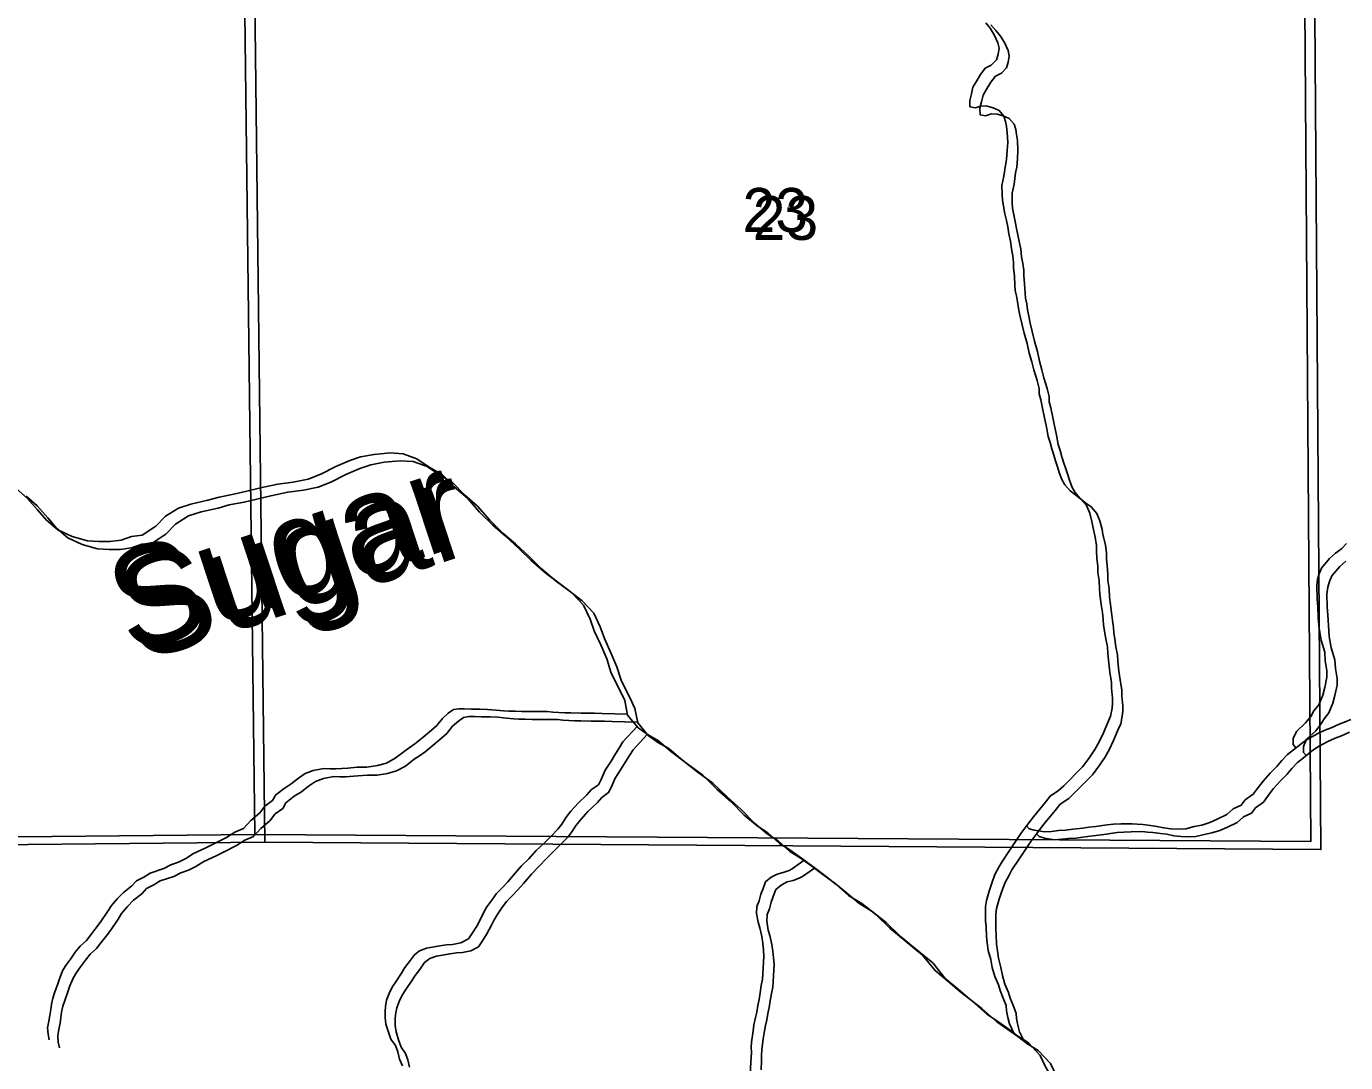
# Model space of a CAD drawing. Extents: x -21.1 to 50.3, y 0 to 22.1.
# Drawn here: x 47.981 to 49.235, y 15.452 to 16.437 of the extents above; entities that cross this region are included whole.
import ezdxf

# ---------------------------------------------------------------- set-up
doc = ezdxf.new("R2010")
doc.units = 0
for name, color, linetype in [('GM_X_Major_River', 7, 'Continuous'), ('GM_X_Major_River_Text', 7, 'Continuous'), ('GM_X_Minor_River', 7, 'Continuous'), ('GM_X_Section', 7, 'Continuous'), ('GM_X_Section_Text', 7, 'Continuous')]:
    doc.layers.add(name, color=color, linetype=linetype)

msp = doc.modelspace()

# ---------------------------------------------------------------- linework, layer by layer
at = {"layer": 'GM_X_Major_River'}
for points in [[(47.9706, 15.998), (47.9813, 15.9886), (47.9913, 15.9773), (47.9997, 15.9675), (48.0104, 15.9584), (48.0241, 15.9521), (48.0386, 15.948), (48.0496, 15.9474), (48.0602, 15.9474), (48.0708, 15.9487), (48.0806, 15.9522), (48.0905, 15.9534), (48.1037, 15.9618), (48.1127, 15.9714), (48.1252, 15.9791), (48.1369, 15.983), (48.1532, 15.9865), (48.1638, 15.9896), (48.1778, 15.9924), (48.19, 15.9951), (48.2032, 15.9983), (48.2195, 16.0018), (48.2343, 16.0038), (48.2483, 16.0066), (48.2604, 16.0112), (48.2748, 16.0186), (48.288, 16.0244), (48.2982, 16.0278), (48.3111, 16.0302), (48.3263, 16.0315), (48.3388, 16.0308), (48.3517, 16.026), (48.3636, 16.0181), (48.3761, 16.0106), (48.3872, 15.9993), (48.3999, 15.9884), (48.4113, 15.9752), (48.424, 15.9628), (48.4358, 15.9527), (48.4492, 15.9402), (48.4603, 15.9293), (48.4748, 15.9169), (48.487, 15.9079), (48.4992, 15.8985), (48.5103, 15.8868), (48.5165, 15.8736), (48.5204, 15.8626), (48.5266, 15.849), (48.5324, 15.8358), (48.5366, 15.8221), (48.5447, 15.8059), (48.5494, 15.7961), (48.5521, 15.7824), (48.5621, 15.7704), (48.5716, 15.7636), (48.5815, 15.758), (48.593, 15.7482), (48.6083, 15.7362), (48.6235, 15.7253), (48.6373, 15.7118), (48.6503, 15.7001), (48.6629, 15.6873), (48.6751, 15.6771), (48.6854, 15.6704), (48.6965, 15.6602), (48.7064, 15.6542), (48.7175, 15.6464), (48.7282, 15.6385), (48.7396, 15.6298), (48.7503, 15.6212), (48.7622, 15.611), (48.7748, 15.6032), (48.7881, 15.5927), (48.8015, 15.5799), (48.816, 15.5678), (48.8325, 15.5543), (48.8443, 15.5396), (48.8566, 15.5294), (48.8676, 15.52), (48.8791, 15.511), (48.8936, 15.4982), (48.9039, 15.4911), (48.9135, 15.4844), (48.923, 15.4772)], [(47.9803, 15.9905), (47.9909, 15.9811), (48.0009, 15.9698), (48.0093, 15.96), (48.02, 15.9509), (48.0337, 15.9446), (48.0482, 15.9405), (48.0592, 15.9399), (48.0698, 15.9399), (48.0804, 15.9412), (48.0903, 15.9447), (48.1001, 15.9459), (48.1133, 15.9543), (48.1224, 15.9639), (48.1348, 15.9716), (48.1466, 15.9754), (48.1629, 15.979), (48.1735, 15.9821), (48.1875, 15.9849), (48.1996, 15.9876), (48.2129, 15.9908), (48.2291, 15.9943), (48.2439, 15.9963), (48.2579, 15.9991), (48.27, 16.0037), (48.2844, 16.0111), (48.2976, 16.0169), (48.3079, 16.0203), (48.3207, 16.0227), (48.3359, 16.024), (48.3484, 16.0233), (48.3614, 16.0185), (48.3732, 16.0106), (48.3858, 16.0031), (48.3969, 15.9918), (48.4095, 15.9809), (48.421, 15.9677), (48.4336, 15.9553), (48.4454, 15.9452), (48.4588, 15.9327), (48.4699, 15.9218), (48.4844, 15.9094), (48.4966, 15.9004), (48.5089, 15.891), (48.52, 15.8793), (48.5261, 15.8661), (48.53, 15.8551), (48.5362, 15.8415), (48.542, 15.8283), (48.5463, 15.8146), (48.5544, 15.7984), (48.559, 15.7886), (48.5618, 15.7749), (48.5717, 15.7629), (48.5813, 15.7561), (48.5912, 15.7505), (48.6026, 15.7407), (48.6179, 15.7287), (48.6332, 15.7178), (48.6469, 15.7043), (48.6599, 15.6926), (48.6726, 15.6798), (48.6848, 15.6696), (48.6951, 15.6629), (48.7062, 15.6527), (48.7161, 15.6467), (48.7271, 15.6389), (48.7378, 15.631), (48.7493, 15.6223), (48.76, 15.6137), (48.7718, 15.6035), (48.7844, 15.5957), (48.7978, 15.5852), (48.8112, 15.5724), (48.8257, 15.5603), (48.8421, 15.5468), (48.854, 15.5321), (48.8662, 15.5219), (48.8773, 15.5125), (48.8887, 15.5035), (48.9032, 15.4907), (48.9136, 15.4836), (48.9231, 15.4769), (48.9326, 15.4697)], [(48.923, 15.4772), (48.9329, 15.4712), (48.9444, 15.4588), (48.9494, 15.4482), (48.9552, 15.438), (48.961, 15.4248), (48.9675, 15.4104), (48.9722, 15.3987), (48.978, 15.3824), (48.9807, 15.3726), (48.9869, 15.3609), (48.9984, 15.3477), (49.0079, 15.3405), (49.0201, 15.3342), (49.0369, 15.3244), (49.0464, 15.3207), (49.0579, 15.3136), (49.0701, 15.3069), (49.0838, 15.3002), (49.1033, 15.2925)], [(48.9326, 15.4697), (48.9425, 15.4637), (48.954, 15.4513), (48.959, 15.4407), (48.9648, 15.4305), (48.9706, 15.4173), (48.9772, 15.4029), (48.9818, 15.3912), (48.9876, 15.3749), (48.9904, 15.3651), (48.9965, 15.3534), (49.008, 15.3402), (49.0176, 15.333), (49.0298, 15.3267), (49.0465, 15.3169), (49.0561, 15.3132), (49.0675, 15.3061), (49.0797, 15.2994), (49.0934, 15.2927), (49.1129, 15.285)]]:
    msp.add_lwpolyline(points, dxfattribs=at)
at = {"layer": 'GM_X_Minor_River'}
for points in [[(48.9182, 16.219), (48.917, 16.2255), (48.9162, 16.2327), (48.9146, 16.2399), (48.9135, 16.2464), (48.9123, 16.2524), (48.9107, 16.2589), (48.9084, 16.2718), (48.908, 16.2771), (48.9079, 16.2858), (48.9098, 16.2946), (48.9112, 16.3052), (48.9123, 16.3105), (48.913, 16.3189), (48.9134, 16.3265), (48.913, 16.336), (48.9122, 16.3417), (48.9114, 16.3466), (48.9098, 16.3516), (48.9052, 16.3569), (48.8995, 16.3595), (48.8938, 16.361), (48.8885, 16.3613), (48.8828, 16.3594), (48.8774, 16.3605), (48.8774, 16.3666), (48.8789, 16.3727), (48.8804, 16.3791), (48.8834, 16.3841), (48.8875, 16.3913), (48.8921, 16.3971), (48.8977, 16.4001), (48.9027, 16.4051), (48.9042, 16.4104), (48.9053, 16.4161), (48.9041, 16.4214), (48.9006, 16.429), (48.8968, 16.4351), (48.8926, 16.4404)], [(48.9278, 16.2115), (48.9266, 16.218), (48.9258, 16.2252), (48.9243, 16.2324), (48.9231, 16.2389), (48.9219, 16.2449), (48.9204, 16.2514), (48.918, 16.2643), (48.9176, 16.2696), (48.9175, 16.2783), (48.9194, 16.2871), (48.9209, 16.2977), (48.922, 16.303), (48.9227, 16.3114), (48.923, 16.319), (48.9226, 16.3285), (48.9218, 16.3342), (48.921, 16.3391), (48.9195, 16.3441), (48.9149, 16.3494), (48.9091, 16.352), (48.9034, 16.3535), (48.8981, 16.3538), (48.8924, 16.3519), (48.8871, 16.353), (48.887, 16.3591), (48.8885, 16.3652), (48.89, 16.3716), (48.893, 16.3766), (48.8972, 16.3838), (48.9017, 16.3896), (48.9074, 16.3926), (48.9123, 16.3976), (48.9138, 16.4029), (48.9149, 16.4086), (48.9137, 16.4139), (48.9103, 16.4215), (48.9064, 16.4276), (48.9022, 16.4329), (48.8972, 16.4385)], [(48.9193, 15.48), (48.915, 15.4889), (48.9135, 15.495), (48.9123, 15.5014), (48.9119, 15.5063), (48.9092, 15.5132), (48.9061, 15.5207), (48.9045, 15.5261), (48.9011, 15.534), (48.8987, 15.5424), (48.8972, 15.55), (48.8948, 15.5587), (48.894, 15.5659), (48.8932, 15.572), (48.8928, 15.5811), (48.8924, 15.5868), (48.8923, 15.6004), (48.8931, 15.6061), (48.8957, 15.6149), (48.8983, 15.6225), (48.9013, 15.6309), (48.9051, 15.6377), (48.9077, 15.6427), (48.9145, 15.6526), (48.9258, 15.6698), (48.9315, 15.6774), (48.9379, 15.6858), (48.9492, 15.6995), (48.9538, 15.7053), (48.9617, 15.7106), (48.9667, 15.7152), (48.9845, 15.7332), (48.9905, 15.7412), (48.9962, 15.7496), (49.0003, 15.7568), (49.0045, 15.7656), (49.0086, 15.7754), (49.0112, 15.7815), (49.0127, 15.7888), (49.013, 15.7937), (49.013, 15.7986), (49.0122, 15.8081), (49.0122, 15.8135), (49.0106, 15.8233), (49.0094, 15.8317), (49.0086, 15.8408), (49.0082, 15.8472), (49.0066, 15.8548), (49.0054, 15.862), (49.0046, 15.8681), (49.0042, 15.8731), (49.0034, 15.8799), (49.0022, 15.8875), (49.001, 15.8973), (49.0006, 15.9023), (49.0002, 15.9103), (48.999, 15.9179), (48.999, 15.9235), (48.9982, 15.9319), (48.9978, 15.938), (48.9977, 15.9437), (48.9966, 15.9516), (48.9942, 15.9615), (48.9934, 15.9664), (48.9915, 15.9744), (48.9884, 15.9816), (48.983, 15.9877), (48.9781, 15.9914), (48.9727, 15.9956), (48.9677, 16.0013), (48.965, 16.0062), (48.9623, 16.013), (48.9608, 16.0183), (48.9589, 16.024), (48.9573, 16.0293), (48.9554, 16.0354), (48.9538, 16.0414), (48.9519, 16.0471), (48.9503, 16.0559), (48.948, 16.0665), (48.9468, 16.0726), (48.9448, 16.082), (48.9433, 16.0877), (48.9432, 16.0927), (48.9413, 16.1003), (48.9382, 16.1105), (48.9362, 16.1181), (48.9339, 16.1264), (48.932, 16.1355), (48.9292, 16.1454), (48.9269, 16.1545), (48.925, 16.1625), (48.9238, 16.1689), (48.9226, 16.175), (48.9218, 16.1807), (48.9206, 16.186), (48.9202, 16.1909), (48.9198, 16.1997), (48.919, 16.2076), (48.919, 16.2126), (48.9182, 16.219)], [(48.929, 15.4725), (48.9247, 15.4814), (48.9231, 15.4875), (48.9219, 15.4939), (48.9215, 15.4988), (48.9188, 15.5057), (48.9157, 15.5132), (48.9142, 15.5186), (48.9107, 15.5265), (48.9084, 15.5349), (48.9068, 15.5425), (48.9045, 15.5512), (48.9037, 15.5584), (48.9029, 15.5645), (48.9025, 15.5736), (48.902, 15.5793), (48.902, 15.5929), (48.9027, 15.5986), (48.9053, 15.6074), (48.9079, 15.615), (48.9109, 15.6234), (48.9147, 15.6302), (48.9173, 15.6352), (48.9241, 15.6451), (48.9355, 15.6623), (48.9411, 15.6699), (48.9475, 15.6783), (48.9589, 15.692), (48.9634, 15.6978), (48.9714, 15.7031), (48.9763, 15.7077), (48.9941, 15.7257), (49.0001, 15.7337), (49.0058, 15.7421), (49.0099, 15.7493), (49.0141, 15.7581), (49.0182, 15.7679), (49.0208, 15.774), (49.0223, 15.7813), (49.0227, 15.7862), (49.0227, 15.7911), (49.0218, 15.8006), (49.0218, 15.806), (49.0202, 15.8158), (49.019, 15.8242), (49.0182, 15.8333), (49.0178, 15.8397), (49.0163, 15.8473), (49.0151, 15.8545), (49.0143, 15.8606), (49.0139, 15.8656), (49.0131, 15.8724), (49.0119, 15.88), (49.0107, 15.8898), (49.0103, 15.8948), (49.0099, 15.9028), (49.0087, 15.9103), (49.0086, 15.916), (49.0078, 15.9244), (49.0074, 15.9305), (49.0074, 15.9362), (49.0062, 15.9441), (49.0039, 15.954), (49.0031, 15.9589), (49.0011, 15.9669), (48.998, 15.9741), (48.9927, 15.9802), (48.9877, 15.9839), (48.9823, 15.9881), (48.9774, 15.9938), (48.9747, 15.9987), (48.972, 16.0055), (48.9704, 16.0108), (48.9685, 16.0165), (48.9669, 16.0218), (48.965, 16.0279), (48.9634, 16.0339), (48.9615, 16.0396), (48.9599, 16.0484), (48.9576, 16.059), (48.9564, 16.0651), (48.9545, 16.0745), (48.9529, 16.0802), (48.9529, 16.0852), (48.9509, 16.0928), (48.9478, 16.103), (48.9459, 16.1106), (48.9436, 16.1189), (48.9416, 16.128), (48.9389, 16.1379), (48.9365, 16.147), (48.9346, 16.155), (48.9334, 16.1614), (48.9322, 16.1675), (48.9315, 16.1732), (48.9303, 16.1785), (48.9299, 16.1834), (48.9294, 16.1922), (48.9286, 16.2001), (48.9286, 16.2051), (48.9278, 16.2115)], [(49.1874, 15.7514), (49.1849, 15.7544), (49.1849, 15.7601), (49.1879, 15.7669), (49.1966, 15.775), (49.2015, 15.7811), (49.2045, 15.7864), (49.2091, 15.7921), (49.2128, 15.8013), (49.2147, 15.8085), (49.2169, 15.8184), (49.2169, 15.8248), (49.2153, 15.834), (49.2149, 15.8423), (49.2114, 15.8537), (49.2094, 15.8647), (49.2086, 15.8749), (49.2082, 15.8848), (49.2074, 15.8928), (49.2073, 15.9049), (49.208, 15.9114), (49.2095, 15.9167), (49.2118, 15.9221), (49.2193, 15.9312), (49.225, 15.9362), (49.2307, 15.9404), (49.2353, 15.9454)], [(49.197, 15.7439), (49.1946, 15.7469), (49.1945, 15.7526), (49.1975, 15.7594), (49.2063, 15.7675), (49.2112, 15.7736), (49.2142, 15.7789), (49.2187, 15.7846), (49.2225, 15.7938), (49.2243, 15.801), (49.2266, 15.8109), (49.2265, 15.8173), (49.225, 15.8265), (49.2245, 15.8348), (49.221, 15.8462), (49.2191, 15.8572), (49.2183, 15.8674), (49.2178, 15.8773), (49.217, 15.8853), (49.2169, 15.8974), (49.2177, 15.9039), (49.2192, 15.9092), (49.2214, 15.9146), (49.229, 15.9237), (49.2347, 15.9287)], [(48.552, 15.7832), (48.5278, 15.7838), (48.5206, 15.7842), (48.508, 15.7841), (48.4981, 15.7844), (48.4924, 15.7844), (48.481, 15.7851), (48.4756, 15.7858), (48.4517, 15.7857), (48.4452, 15.786), (48.4391, 15.786), (48.4341, 15.7864), (48.4273, 15.7871), (48.4189, 15.7878), (48.4117, 15.7881), (48.4037, 15.7881), (48.3968, 15.7884), (48.3915, 15.7884), (48.3866, 15.7876), (48.3816, 15.7842), (48.376, 15.7792), (48.3707, 15.7724), (48.3657, 15.7681), (48.3578, 15.7613), (48.3498, 15.7551), (48.3445, 15.7513), (48.3396, 15.7479), (48.3312, 15.7414), (48.3229, 15.7368), (48.3142, 15.7344), (48.3043, 15.7329), (48.2951, 15.7328), (48.286, 15.732), (48.2746, 15.7312), (48.2689, 15.7312), (48.2632, 15.7315), (48.2533, 15.7296), (48.2457, 15.7269), (48.2392, 15.7223), (48.2324, 15.7169), (48.2256, 15.7127), (48.2176, 15.7066), (48.2146, 15.7012), (48.2074, 15.6959), (48.2025, 15.6894), (48.1938, 15.6821), (48.187, 15.6745), (48.1786, 15.671), (48.1707, 15.666), (48.1589, 15.6599), (48.1513, 15.6561), (48.1395, 15.6507), (48.132, 15.6461), (48.1251, 15.6426), (48.1179, 15.6399), (48.1111, 15.6365), (48.0982, 15.6322), (48.0921, 15.6284), (48.0853, 15.6249), (48.0807, 15.62), (48.0728, 15.6139), (48.0671, 15.6081), (48.0614, 15.6013), (48.058, 15.5959), (48.0508, 15.5852), (48.0467, 15.5799), (48.0418, 15.5734), (48.0376, 15.5681), (48.0316, 15.5627), (48.027, 15.557), (48.0225, 15.5505), (48.0187, 15.5452), (48.0153, 15.5399), (48.0123, 15.5326), (48.0104, 15.5269), (48.0074, 15.5185), (48.0056, 15.5132), (48.0045, 15.5075), (48.0037, 15.5026), (48.003, 15.4969), (48.0019, 15.4915), (48.0008, 15.4851), (48.0012, 15.479), (48.0024, 15.4737)], [(48.5616, 15.7757), (48.5374, 15.7763), (48.5302, 15.7767), (48.5176, 15.7766), (48.5077, 15.7769), (48.502, 15.7769), (48.4906, 15.7776), (48.4853, 15.7783), (48.4613, 15.7782), (48.4548, 15.7785), (48.4487, 15.7785), (48.4438, 15.7789), (48.4369, 15.7796), (48.4286, 15.7803), (48.4213, 15.7806), (48.4133, 15.7806), (48.4065, 15.7809), (48.4011, 15.7809), (48.3962, 15.7801), (48.3913, 15.7767), (48.3856, 15.7717), (48.3803, 15.7649), (48.3754, 15.7606), (48.3674, 15.7538), (48.3595, 15.7476), (48.3542, 15.7438), (48.3492, 15.7404), (48.3409, 15.7339), (48.3325, 15.7293), (48.3238, 15.7269), (48.3139, 15.7254), (48.3048, 15.7253), (48.2956, 15.7245), (48.2842, 15.7237), (48.2785, 15.7237), (48.2728, 15.724), (48.2629, 15.7221), (48.2553, 15.7194), (48.2489, 15.7148), (48.2421, 15.7094), (48.2352, 15.7052), (48.2273, 15.6991), (48.2243, 15.6937), (48.2171, 15.6884), (48.2121, 15.6819), (48.2034, 15.6746), (48.1966, 15.667), (48.1883, 15.6635), (48.1803, 15.6585), (48.1685, 15.6524), (48.1609, 15.6486), (48.1492, 15.6432), (48.1416, 15.6386), (48.1348, 15.6351), (48.1275, 15.6324), (48.1207, 15.629), (48.1078, 15.6247), (48.1017, 15.6209), (48.0949, 15.6174), (48.0904, 15.6125), (48.0824, 15.6064), (48.0767, 15.6006), (48.071, 15.5938), (48.0677, 15.5884), (48.0605, 15.5777), (48.0563, 15.5724), (48.0514, 15.5659), (48.0473, 15.5606), (48.0412, 15.5552), (48.0367, 15.5495), (48.0321, 15.543), (48.0283, 15.5377), (48.025, 15.5324), (48.0219, 15.5251), (48.0201, 15.5194), (48.0171, 15.511), (48.0152, 15.5057), (48.0141, 15.5), (48.0134, 15.4951), (48.0126, 15.4894), (48.0115, 15.484), (48.0104, 15.4776), (48.0108, 15.4715), (48.012, 15.4662)], [(48.9312, 15.677), (48.9338, 15.6744), (48.9387, 15.6729), (48.9483, 15.6714), (48.9551, 15.6718), (48.9616, 15.6726), (48.9684, 15.673), (48.9753, 15.6738), (48.9848, 15.675), (48.9905, 15.6758), (48.9973, 15.6766), (49.008, 15.6782), (49.0141, 15.6786), (49.0209, 15.679), (49.0316, 15.6791), (49.0365, 15.6787), (49.0419, 15.6784), (49.0491, 15.6773), (49.0552, 15.6766), (49.0617, 15.6751), (49.0685, 15.6744), (49.075, 15.674), (49.0826, 15.6744), (49.0906, 15.6764), (49.0978, 15.6779), (49.1054, 15.6803), (49.1126, 15.6833), (49.1217, 15.6879), (49.1278, 15.6933), (49.1354, 15.6968), (49.1392, 15.7017), (49.1468, 15.7071), (49.1505, 15.7124), (49.1562, 15.7197), (49.163, 15.7273), (49.1691, 15.7334), (49.174, 15.7391), (49.1793, 15.7449), (49.185, 15.7495), (49.1922, 15.7552), (49.1975, 15.759), (49.2032, 15.7621), (49.2081, 15.7648), (49.2149, 15.7679), (49.221, 15.7702), (49.2286, 15.7736), (49.2335, 15.7756), (49.2396, 15.7782)], [(48.5612, 15.7715), (48.5477, 15.757), (48.5443, 15.7516), (48.5406, 15.7455), (48.5364, 15.7387), (48.5308, 15.7299), (48.527, 15.7212), (48.5244, 15.7162), (48.5179, 15.7116), (48.5134, 15.7066), (48.5047, 15.6982), (48.4982, 15.691), (48.4937, 15.6853), (48.4896, 15.6788), (48.4858, 15.6738), (48.4797, 15.6677), (48.4722, 15.6601), (48.4653, 15.6536), (48.4582, 15.6459), (48.451, 15.6387), (48.4434, 15.6299), (48.4381, 15.6238), (48.4332, 15.6185), (48.4275, 15.6127), (48.423, 15.6066), (48.4184, 15.6001), (48.4154, 15.5952), (48.4132, 15.5902), (48.4087, 15.5819), (48.4045, 15.5754), (48.4007, 15.5697), (48.3935, 15.5658), (48.3855, 15.5643), (48.3798, 15.5639), (48.3737, 15.5631), (48.3608, 15.5607), (48.3544, 15.5584), (48.3494, 15.5546), (48.3449, 15.5481), (48.3404, 15.5424), (48.337, 15.537), (48.3317, 15.529), (48.3283, 15.5237), (48.3253, 15.5176), (48.323, 15.5115), (48.3219, 15.5054), (48.3216, 15.5005), (48.3216, 15.4948), (48.3224, 15.4887), (48.3247, 15.4811), (48.327, 15.4743), (48.3313, 15.4682), (48.3336, 15.4622), (48.3351, 15.4553), (48.3382, 15.4489)], [(48.5708, 15.764), (48.5574, 15.7495), (48.554, 15.7441), (48.5502, 15.738), (48.5461, 15.7312), (48.5404, 15.7224), (48.5366, 15.7137), (48.534, 15.7087), (48.5276, 15.7041), (48.523, 15.6991), (48.5143, 15.6907), (48.5079, 15.6835), (48.5033, 15.6778), (48.4992, 15.6713), (48.4954, 15.6663), (48.4894, 15.6602), (48.4818, 15.6526), (48.475, 15.6461), (48.4678, 15.6384), (48.4606, 15.6312), (48.453, 15.6224), (48.4477, 15.6163), (48.4428, 15.611), (48.4371, 15.6052), (48.4326, 15.5991), (48.4281, 15.5926), (48.4251, 15.5877), (48.4228, 15.5827), (48.4183, 15.5744), (48.4141, 15.5679), (48.4104, 15.5622), (48.4032, 15.5583), (48.3952, 15.5568), (48.3895, 15.5564), (48.3834, 15.5556), (48.3704, 15.5532), (48.364, 15.5509), (48.3591, 15.5471), (48.3545, 15.5406), (48.35, 15.5349), (48.3466, 15.5295), (48.3413, 15.5215), (48.3379, 15.5162), (48.3349, 15.5101), (48.3327, 15.504), (48.3316, 15.4979), (48.3312, 15.493), (48.3312, 15.4873), (48.332, 15.4812), (48.3344, 15.4736), (48.3367, 15.4668), (48.3409, 15.4607), (48.3432, 15.4547), (48.3448, 15.4478)], [(48.9408, 15.6695), (48.9434, 15.6669), (48.9484, 15.6654), (48.9579, 15.6639), (48.9647, 15.6643), (48.9712, 15.6651), (48.9781, 15.6655), (48.9849, 15.6663), (48.9944, 15.6675), (49.0001, 15.6683), (49.007, 15.6691), (49.0176, 15.6707), (49.0237, 15.6711), (49.0306, 15.6715), (49.0412, 15.6716), (49.0462, 15.6712), (49.0515, 15.6709), (49.0587, 15.6698), (49.0648, 15.6691), (49.0713, 15.6676), (49.0782, 15.6669), (49.0846, 15.6665), (49.0922, 15.6669), (49.1002, 15.6689), (49.1075, 15.6704), (49.1151, 15.6728), (49.1223, 15.6758), (49.1314, 15.6804), (49.1374, 15.6858), (49.145, 15.6893), (49.1488, 15.6942), (49.1564, 15.6996), (49.1602, 15.7049), (49.1658, 15.7122), (49.1726, 15.7198), (49.1787, 15.7259), (49.1836, 15.7316), (49.1889, 15.7374), (49.1946, 15.7419), (49.2018, 15.7477), (49.2071, 15.7515), (49.2128, 15.7546), (49.2177, 15.7573), (49.2246, 15.7603), (49.2306, 15.7627), (49.2382, 15.7661)], [(48.72, 15.6445), (48.7086, 15.6363), (48.7056, 15.6348), (48.6999, 15.6328), (48.6942, 15.6313), (48.6885, 15.6282), (48.6832, 15.624), (48.681, 15.6175), (48.6787, 15.6122), (48.6772, 15.6057), (48.675, 15.6004), (48.6746, 15.5939), (48.6762, 15.5856), (48.6778, 15.5803), (48.6797, 15.5719), (48.6805, 15.5655), (48.6813, 15.559), (48.6817, 15.553), (48.6814, 15.5476), (48.6807, 15.5362), (48.6803, 15.5313), (48.6792, 15.5252), (48.6781, 15.5184), (48.677, 15.5119), (48.6759, 15.5062), (48.6748, 15.5001), (48.6737, 15.4948), (48.6722, 15.4879), (48.6715, 15.4822), (48.67, 15.4716), (48.6696, 15.4667), (48.6697, 15.4617), (48.6693, 15.4526), (48.6686, 15.4408)], [(48.7296, 15.637), (48.7182, 15.6288), (48.7153, 15.6273), (48.7096, 15.6253), (48.7039, 15.6238), (48.6982, 15.6207), (48.6929, 15.6165), (48.6906, 15.61), (48.6884, 15.6047), (48.6869, 15.5982), (48.6846, 15.5929), (48.6843, 15.5864), (48.6858, 15.5781), (48.6874, 15.5728), (48.6893, 15.5644), (48.6901, 15.558), (48.6909, 15.5515), (48.6914, 15.5455), (48.691, 15.5401), (48.6903, 15.5287), (48.69, 15.5238), (48.6888, 15.5177), (48.6877, 15.5109), (48.6866, 15.5044), (48.6855, 15.4987), (48.6844, 15.4926), (48.6833, 15.4873), (48.6818, 15.4804), (48.6811, 15.4747), (48.6796, 15.4641), (48.6793, 15.4592), (48.6793, 15.4542), (48.679, 15.4451)]]:
    msp.add_lwpolyline(points, dxfattribs=at)
at = {"layer": 'GM_X_Section'}
for points in [[(47.1739, 16.679), (48.1855, 16.6839), (48.1977, 15.669), (47.1998, 15.6592), (47.1908, 16.2808)], [(48.1855, 16.6839), (48.6942, 16.687), (49.1942, 16.6763), (49.2014, 15.6621), (48.1977, 15.669)], [(48.1952, 16.6764), (48.7038, 16.6795), (49.2038, 16.6688), (49.2111, 15.6546), (48.2073, 15.6615)], [(47.1836, 16.6715), (48.1952, 16.6764), (48.2073, 15.6615), (47.2094, 15.6517), (47.2004, 16.2733)]]:
    msp.add_lwpolyline(points, close=True, dxfattribs=at)

# ---------------------------------------------------------------- texts
at = {"layer": 'GM_X_Major_River_Text'}
for p in [(48.079, 15.8396), (48.0886, 15.8321)]:
    msp.add_text('Sugar', height=0.09471, rotation=18.3109, dxfattribs=at).set_placement(p)
at = {"layer": 'GM_X_Section_Text'}
for p in [(48.6613, 16.2415), (48.671, 16.234)]:
    msp.add_text('23', height=0.04186, rotation=0, dxfattribs=at).set_placement(p)

doc.saveas('drawing.dxf')
